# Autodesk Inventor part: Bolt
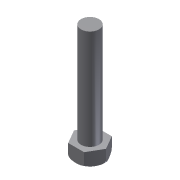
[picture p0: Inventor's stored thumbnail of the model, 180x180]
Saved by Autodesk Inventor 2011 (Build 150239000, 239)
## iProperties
Shininess: 77.0
Length Units: 11269
Angle Units: 11279
Time Units: 11290
Mass Units: 11283
Length Display Precision: 3
Angle Display Precision: 2
Created: 2002-02
Part Number: Bolt
Document SubType Name: Modeling
Designer: ***
Density: 1 g/cm^3
Density: 0.0
Volumn: 0.0
Area: 0.0
PropertySet Name: Model Information
Control State: 0
Master: False
Checked Out: False
Author: ***
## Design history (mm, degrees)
sketch "Sketch1"
  geometry: C1 r 4 at (0, 0)
  constraints: 1 centre point
  dimensions: "d0" = 8 diameter of C1
extrude "Extrusion1" new body sketch "Sketch1" stored distance "d1" = 3.5; taper "d2" = 0 deg
fillet "Fillet1" dims "d3" = 1
sketch "Sketch2"
  geometry: L1 (4, 0)-(2, -3.464); L2 (2, -3.464)-(-2, -3.464); L3 (-2, -3.464)-(-4, 0); L4 (-4, 0)-(-2, 3.464); L5 (-2, 3.464)-(2, 3.464); L6 (2, 3.464)-(4, 0); 2 further points
  constraints: 12 end point, 1 coincident, 11 other
extrude "Extrusion2" sketch "Sketch2" stored distance "d4" = 3.5; taper "d5" = 0 deg
sketch "Sketch3"
  geometry: C1 r 2.25 at (0, 0)
  constraints: 1 centre point
  dimensions: "d6" = 4.5 diameter of C1
extrude "Extrusion3" join sketch "Sketch3" distance "d7" = 25; taper "d8" = 0 deg
body "Solid1"
